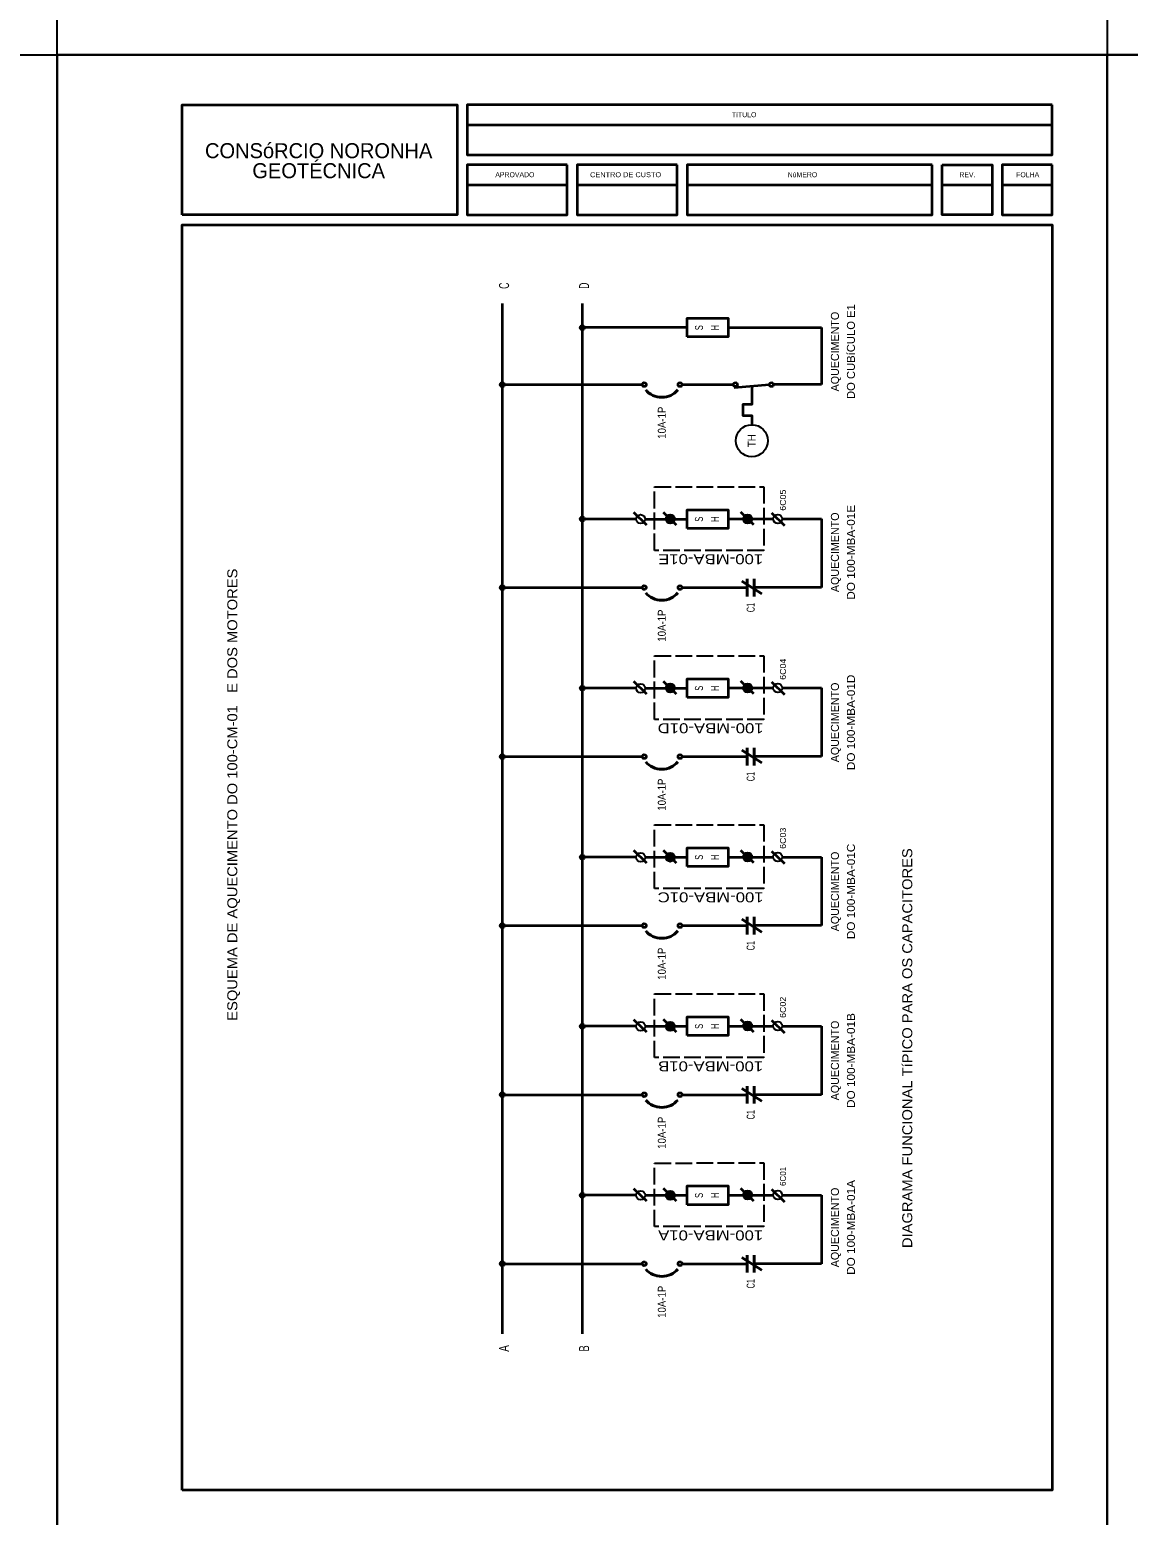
# Model space of a CAD drawing. Extents: x -4160 to -2690, y -474 to 714.
# Drawn here: x -3535.3 to -3315.6, y -171.5 to 125.5 of the extents above; entities that cross this region are included whole.
import ezdxf
from ezdxf.enums import TextEntityAlignment as Align

# ---------------------------------------------------------------- set-up
doc = ezdxf.new("R2010")
doc.units = 0
doc.header["$LTSCALE"] = 0.56
doc.linetypes.add('LONG_DASHED', pattern=[7.5, 6, -1.5])
doc.layers.add('2', color=7, linetype='Continuous', lineweight=25)
doc.layers.add('5', color=7, linetype='Continuous', lineweight=35)

msp = doc.modelspace()

# ---------------------------------------------------------------- hatches: boundary and pattern name
at = {"layer": '2'}
for points in [[(-3424.7533, 66.344, 1), (-3424.7533, 65.5189, 1)], [(-3440.7533, 54.931, 1), (-3440.7533, 54.1058, 1)], [(-3424.7533, 28.0555, 1), (-3424.7533, 27.2304, 1)], [(-3407.1695, 26.7464, 1), (-3407.1695, 28.5446, 1)], [(-3391.6888, 26.7816, 1), (-3391.6888, 28.5798, 1)], [(-3440.7533, 14.3678, 1), (-3440.7533, 13.5426, 1)], [(-3424.7533, -5.742, 1), (-3424.7533, -6.5671, 1)], [(-3407.1695, -7.0511, 1), (-3407.1695, -5.2529, 1)], [(-3391.6888, -7.0159, 1), (-3391.6888, -5.2177, 1)], [(-3440.7533, -19.4297, 1), (-3440.7533, -20.2549, 1)], [(-3424.7533, -39.5395, 1), (-3424.7533, -40.3647, 1)], [(-3407.1695, -40.8486, 1), (-3407.1695, -39.0504, 1)], [(-3391.6888, -40.8134, 1), (-3391.6888, -39.0152, 1)], [(-3440.7533, -53.2273, 1), (-3440.7533, -54.0524, 1)], [(-3424.7533, -73.337, 1), (-3424.7533, -74.1622, 1)], [(-3407.1695, -74.6461, 1), (-3407.1695, -72.848, 1)], [(-3391.6888, -74.6109, 1), (-3391.6888, -72.8128, 1)], [(-3440.7533, -87.0248, 1), (-3440.7533, -87.8499, 1)], [(-3407.1695, -108.4436, 1), (-3407.1695, -106.6455, 1)], [(-3391.6888, -108.4084, 1), (-3391.6888, -106.6103, 1)], [(-3424.7533, -107.1345, 1), (-3424.7533, -107.9597, 1)], [(-3440.7533, -120.8223, 1), (-3440.7533, -121.6475, 1)]]:
    msp.add_hatch(color=256, dxfattribs=at).paths.add_polyline_path(points)

# ---------------------------------------------------------------- linework, layer by layer
at = {"layer": '2', "lineweight": 35}
for p, q in [((-3440.7533, 70.7423), (-3440.7533, -135.2357)), ((-3424.7533, 70.7423), (-3424.7533, -135.2357)), ((-3403.7624, 65.9314), (-3424.7533, 65.9314)), ((-3395.5781, 65.9314), (-3376.9079, 65.9314)), ((-3376.9079, 65.9314), (-3376.9079, 54.5184)), ((-3440.7533, 54.5184), (-3412.7734, 54.5184)), ((-3404.8113, 54.5184), (-3394.5291, 54.5184)), ((-3387.3277, 54.4831), (-3394.3915, 53.8577)), ((-3376.9079, 54.5184), (-3386.5293, 54.5184)), ((-3413.981, 27.643), (-3424.7533, 27.643)), ((-3414.5149, 29.0213), (-3411.918, 26.5035)), ((-3412.183, 27.643), (-3403.7624, 27.643)), ((-3408.6024, 29.037), (-3406.0055, 26.5192)), ((-3395.5782, 27.6782), (-3386.5615, 27.6782)), ((-3393.1217, 29.0722), (-3390.5248, 26.5544)), ((-3384.2295, 26.2867), (-3386.8264, 28.8045)), ((-3384.7633, 27.6782), (-3376.9079, 27.6782)), ((-3376.9079, 27.6782), (-3376.9079, 13.9552)), ((-3392.8766, 15.2282), (-3388.8426, 12.6823)), ((-3440.7533, 13.9552), (-3412.7734, 13.9552)), ((-3404.8113, 13.9552), (-3391.8087, 13.9552)), ((-3376.9079, 13.9552), (-3390.3559, 13.9552)), ((-3414.5149, -4.7762), (-3411.918, -7.294)), ((-3408.6024, -4.7606), (-3406.0055, -7.2783)), ((-3393.1217, -4.7254), (-3390.5248, -7.2431)), ((-3384.2295, -7.5108), (-3386.8264, -4.993)), ((-3413.981, -6.1546), (-3424.7533, -6.1546)), ((-3412.183, -6.1546), (-3403.7624, -6.1546)), ((-3395.5782, -6.1194), (-3386.5615, -6.1194)), ((-3384.7633, -6.1194), (-3376.9079, -6.1194)), ((-3376.9079, -6.1194), (-3376.9079, -19.8423)), ((-3440.7533, -19.8423), (-3412.7734, -19.8423)), ((-3404.8113, -19.8423), (-3391.8087, -19.8423)), ((-3392.8766, -18.5694), (-3388.8426, -21.1152)), ((-3376.9079, -19.8423), (-3390.3559, -19.8423)), ((-3414.5149, -38.5738), (-3411.918, -41.0915)), ((-3408.6024, -38.5581), (-3406.0055, -41.0758)), ((-3393.1217, -38.5229), (-3390.5248, -41.0406)), ((-3413.981, -39.9521), (-3424.7533, -39.9521)), ((-3412.183, -39.9521), (-3403.7624, -39.9521)), ((-3395.5782, -39.9169), (-3386.5615, -39.9169)), ((-3384.2295, -41.3083), (-3386.8264, -38.7906)), ((-3384.7633, -39.9169), (-3376.9079, -39.9169)), ((-3376.9079, -39.9169), (-3376.9079, -53.6398)), ((-3392.8766, -52.3669), (-3388.8426, -54.9127)), ((-3440.7533, -53.6398), (-3412.7734, -53.6398)), ((-3404.8113, -53.6398), (-3391.8087, -53.6398)), ((-3376.9079, -53.6398), (-3390.3559, -53.6398)), ((-3413.981, -73.7496), (-3424.7533, -73.7496)), ((-3414.5149, -72.3713), (-3411.918, -74.889)), ((-3412.183, -73.7496), (-3403.7624, -73.7496)), ((-3408.6024, -72.3556), (-3406.0055, -74.8734)), ((-3395.5782, -73.7144), (-3386.5615, -73.7144)), ((-3393.1217, -72.3204), (-3390.5248, -74.8382)), ((-3384.2295, -75.1058), (-3386.8264, -72.5881)), ((-3384.7633, -73.7144), (-3376.9079, -73.7144)), ((-3376.9079, -73.7144), (-3376.9079, -87.4374)), ((-3440.7533, -87.4374), (-3412.7734, -87.4374)), ((-3404.8113, -87.4374), (-3391.8087, -87.4374)), ((-3392.8766, -86.1644), (-3388.8426, -88.7102)), ((-3376.9079, -87.4374), (-3390.3559, -87.4374)), ((-3414.5149, -106.1688), (-3411.918, -108.6866)), ((-3408.6024, -106.1531), (-3406.0055, -108.6709)), ((-3393.1217, -106.1179), (-3390.5248, -108.6357)), ((-3384.2295, -108.9034), (-3386.8264, -106.3856)), ((-3413.981, -107.5471), (-3424.7533, -107.5471)), ((-3412.183, -107.5471), (-3403.7624, -107.5471)), ((-3395.5782, -107.5119), (-3386.5615, -107.5119)), ((-3384.7633, -107.5119), (-3376.9079, -107.5119)), ((-3376.9079, -107.5119), (-3376.9079, -121.2349)), ((-3440.7533, -121.2349), (-3412.7734, -121.2349)), ((-3404.8113, -121.2349), (-3391.8087, -121.2349)), ((-3392.8766, -119.9619), (-3388.8426, -122.5078)), ((-3376.9079, -121.2349), (-3390.3559, -121.2349))]:
    msp.add_line(p, q, dxfattribs=at)
at = {"layer": '2', "lineweight": 40}
for p, q in [((-3391.8087, 12.1981), (-3391.8087, 15.6966)), ((-3390.3559, 12.1981), (-3390.3559, 15.6966)), ((-3391.8087, -21.5994), (-3391.8087, -18.1009)), ((-3390.3559, -21.5994), (-3390.3559, -18.1009)), ((-3391.8087, -55.397), (-3391.8087, -51.8984)), ((-3390.3559, -55.397), (-3390.3559, -51.8984)), ((-3391.8087, -89.1945), (-3391.8087, -85.6959)), ((-3390.3559, -89.1945), (-3390.3559, -85.6959)), ((-3391.8087, -122.992), (-3391.8087, -119.4934)), ((-3390.3559, -122.992), (-3390.3559, -119.4934))]:
    msp.add_line(p, q, dxfattribs=at)
at = {"layer": '2', "lineweight": 35}
for points in [[(-3403.7623, 64.0556), (-3403.7623, 67.8072), (-3395.5781, 67.8072), (-3395.5781, 64.0556)], [(-3403.7624, 25.7671), (-3403.7624, 29.5187), (-3395.5782, 29.5187), (-3395.5782, 25.7671)], [(-3403.7624, -8.0304), (-3403.7624, -4.2788), (-3395.5782, -4.2788), (-3395.5782, -8.0304)], [(-3403.7624, -41.8279), (-3403.7624, -38.0763), (-3395.5782, -38.0763), (-3395.5782, -41.8279)], [(-3403.7624, -75.6254), (-3403.7624, -71.8738), (-3395.5782, -71.8738), (-3395.5782, -75.6254)], [(-3403.7624, -109.423), (-3403.7624, -105.6714), (-3395.5782, -105.6714), (-3395.5782, -109.423)]]:
    msp.add_lwpolyline(points, close=True, dxfattribs=at)
msp.add_lwpolyline([(-3390.8596, 54.1704), (-3390.8596, 50.5766), (-3392.6703, 50.5766), (-3392.6703, 48.3522), (-3390.8596, 48.3636), (-3390.8596, 46.5087)], dxfattribs=at)
at = {"layer": '2', "linetype": 'LONG_DASHED'}
for points in [[(-3410.3205, 21.3845), (-3410.3205, 34.0927), (-3388.4367, 34.1148), (-3388.4239, 21.3845)], [(-3410.3205, -12.413), (-3410.3205, 0.2952), (-3388.4367, 0.3173), (-3388.4239, -12.413)], [(-3410.3205, -46.2106), (-3410.3205, -33.5023), (-3388.4367, -33.4802), (-3388.4239, -46.2106)], [(-3410.3205, -80.0081), (-3410.3205, -67.2998), (-3388.4367, -67.2778), (-3388.4239, -80.0081)], [(-3410.3205, -113.8056), (-3410.3205, -101.0974), (-3388.4367, -101.0753), (-3388.4239, -113.8056)]]:
    msp.add_lwpolyline(points, close=True, dxfattribs=at)
at = {"layer": '2', "lineweight": 35}
for centre, radius in [((-3424.7533, 65.9314), 0.4126), ((-3440.7533, 54.5184), 0.4126), ((-3412.3734, 54.5184), 0.4), ((-3405.2113, 54.5184), 0.4), ((-3394.1291, 54.5184), 0.4), ((-3386.9292, 54.5184), 0.4), ((-3424.7533, 27.643), 0.4126), ((-3440.7533, 13.9552), 0.4126), ((-3412.3734, 13.9552), 0.4), ((-3405.2113, 13.9552), 0.4), ((-3424.7533, -6.1546), 0.4126), ((-3440.7533, -19.8423), 0.4126), ((-3412.3734, -19.8423), 0.4), ((-3405.2113, -19.8424), 0.4), ((-3424.7533, -39.9521), 0.4126), ((-3440.7533, -53.6398), 0.4126), ((-3412.3734, -53.6398), 0.4), ((-3405.2113, -53.6399), 0.4), ((-3424.7533, -73.7496), 0.4126), ((-3440.7533, -87.4374), 0.4126), ((-3412.3734, -87.4373), 0.4), ((-3405.2113, -87.4374), 0.4), ((-3424.7533, -107.5471), 0.4126), ((-3440.7533, -121.2349), 0.4126), ((-3412.3734, -121.2348), 0.4), ((-3405.2113, -121.2349), 0.4)]:
    msp.add_circle(centre, radius, dxfattribs=at)
at = {"layer": '2'}
for centre, radius in [((-3390.8596, 43.3104), 3.1984), ((-3413.082, 27.6298), 0.8991), ((-3407.1695, 27.6455), 0.8991), ((-3391.6888, 27.6807), 0.8991), ((-3385.6624, 27.6782), 0.8991), ((-3413.082, -6.1677), 0.8991), ((-3407.1695, -6.152), 0.8991), ((-3391.6888, -6.1168), 0.8991), ((-3385.6624, -6.1194), 0.8991), ((-3413.082, -39.9652), 0.8991), ((-3407.1695, -39.9495), 0.8991), ((-3391.6888, -39.9143), 0.8991), ((-3385.6624, -39.9169), 0.8991), ((-3413.082, -73.7627), 0.8991), ((-3407.1695, -73.747), 0.8991), ((-3391.6888, -73.7118), 0.8991), ((-3385.6624, -73.7144), 0.8991), ((-3413.082, -107.5602), 0.8991), ((-3407.1695, -107.5446), 0.8991), ((-3391.6888, -107.5094), 0.8991), ((-3385.6624, -107.5119), 0.8991)]:
    msp.add_circle(centre, radius, dxfattribs=at)
at = {"layer": '2', "lineweight": 40}
for centre in [(-3408.8584, 55.2333), (-3408.8584, 14.6701), (-3408.8584, -19.1274), (-3408.8584, -52.9249), (-3408.8584, -86.7224), (-3408.8584, -120.5199)]:
    msp.add_ellipse(centre, major_axis=(-3.8115, 0), ratio=0.85, start_param=0.57974073, end_param=2.56185197, dxfattribs=at)
at = {"layer": '5', "lineweight": 25}
for p, q in [((-3529.7642, 120.48), (-3529.7642, 417.4797)), ((-3319.7642, 417.48), (-3319.7642, 120.48)), ((-3739.7642, 120.48), (-3529.7642, 120.48)), ((-3319.7642, 120.48), (-3529.7642, 120.48)), ((-3529.7642, -176.52), (-3529.7642, 120.48)), ((-3529.7642, 120.48), (-3529.7642, -176.52)), ((-3109.7642, 120.48), (-3319.7642, 120.48))]:
    msp.add_line(p, q, dxfattribs=at)
at = {"layer": '5'}
for p, q in [((-3447.7642, 106.48), (-3330.7642, 106.48)), ((-3447.7642, 94.48), (-3427.7642, 94.48)), ((-3425.7642, 94.48), (-3405.7642, 94.48)), ((-3403.7642, 94.48), (-3354.7642, 94.48)), ((-3352.7642, 94.48), (-3342.7642, 94.48)), ((-3340.7642, 94.48), (-3330.7642, 94.48))]:
    msp.add_line(p, q, dxfattribs=at)
at = {"layer": '5', "lineweight": 25}
msp.add_lwpolyline([(-3529.7642, 417.48), (-3319.7642, 417.48), (-3319.7642, 120.48)], dxfattribs=at)
for points in [[(-3319.7642, -176.52), (-3529.7642, -176.52), (-3529.7642, 120.48), (-3319.7642, 120.48)], [(-3109.7642, -176.52), (-3319.7642, -176.52), (-3319.7642, 120.48), (-3109.7642, 120.48)]]:
    msp.add_lwpolyline(points, close=True, dxfattribs=at)
at = {"layer": '5'}
for points in [[(-3504.7642, 88.48), (-3504.7642, 110.48), (-3449.7642, 110.48), (-3449.7642, 88.48)], [(-3330.7642, 110.48), (-3447.7642, 110.48), (-3447.7642, 100.48), (-3330.7642, 100.48)], [(-3427.7642, 98.48), (-3447.7642, 98.48), (-3447.7642, 88.48), (-3427.7642, 88.48)], [(-3405.7642, 98.48), (-3425.7642, 98.48), (-3425.7642, 88.48), (-3405.7642, 88.48)], [(-3354.7642, 98.48), (-3403.7642, 98.48), (-3403.7642, 88.48), (-3354.7642, 88.48)], [(-3352.7642, 98.48), (-3342.7642, 98.48), (-3342.7642, 88.48), (-3352.7642, 88.48)], [(-3330.7642, 98.48), (-3340.7642, 98.48), (-3340.7642, 88.48), (-3330.7642, 88.48)], [(-3504.7642, -166.52), (-3504.7642, 86.48), (-3330.7642, 86.48), (-3330.7642, -166.52)]]:
    msp.add_lwpolyline(points, close=True, dxfattribs=at)

# ---------------------------------------------------------------- texts
at = {"layer": '2'}
for s, height, rotation, width, p in [('C', 2, 90, 0.65, (-3439.4011, 74.2965)), ('D', 2, 90, 0.65, (-3423.4011, 74.2965)), ('DO CUBíCULO E1', 1.6, 90, 1.05, (-3370.2333, 61.1305)), ('S', 1.6, 90, 0.7, (-3400.6274, 65.9142)), ('H', 1.6, 90, 0.6, (-3397.4274, 65.9125)), ('10A-1P', 1.6, 90, 0.9, (-3408.0544, 46.9099)), ('TH', 1.6, 90, 0.9, (-3390.0597, 43.3103)), ('6C05', 1.2, 90, 1.1, (-3384.0321, 31.4268)), ('DO 100-MBA-01E', 1.6, 90, 1.1, (-3370.2333, 21.0051)), ('S', 1.6, 90, 0.7, (-3400.6275, 27.6257)), ('H', 1.6, 90, 0.6, (-3397.4275, 27.624)), ('100-MBA-01E', 2, 180, 1.25, (-3399.0881, 20.6254)), ('ESQUEMA DE AQUECIMENTO DO 100-CM-01   E DOS MOTORES', 2, 90, 1.1, (-3493.7471, -27.4534)), ('10A-1P', 1.6, 90, 0.9, (-3408.0544, 6.3467)), ('C1', 1.6, 90, 0.55, (-3390.2844, 9.9611)), ('6C04', 1.2, 90, 1.1, (-3384.0321, -2.3708)), ('S', 1.6, 90, 0.7, (-3400.6275, -6.1718)), ('H', 1.6, 90, 0.6, (-3397.4275, -6.1735)), ('DO 100-MBA-01D', 1.6, 90, 1.1, (-3370.2333, -13.0044)), ('100-MBA-01D', 2, 180, 1.25, (-3399.0882, -13.1722)), ('C1', 1.6, 90, 0.55, (-3390.2844, -23.8365)), ('10A-1P', 1.6, 90, 0.9, (-3408.0544, -27.4508)), ('6C03', 1.2, 90, 1.1, (-3384.0321, -36.1683)), ('DO 100-MBA-01C', 1.6, 90, 1.1, (-3370.2333, -46.802)), ('DIAGRAMA FUNCIONAL TíPICO PARA OS CAPACITORES', 2, 90, 1.1, (-3358.7702, -78.1262)), ('S', 1.6, 90, 0.7, (-3400.6275, -39.9693)), ('H', 1.6, 90, 0.6, (-3397.4275, -39.971)), ('100-MBA-01C', 2, 180, 1.25, (-3399.0882, -46.9697)), ('10A-1P', 1.6, 90, 0.9, (-3408.0544, -61.2483)), ('C1', 1.6, 90, 0.55, (-3390.2844, -57.634)), ('6C02', 1.2, 90, 1.1, (-3384.0321, -69.9658)), ('DO 100-MBA-01B', 1.6, 90, 1.1, (-3370.2333, -80.5994)), ('S', 1.6, 90, 0.7, (-3400.6275, -73.7668)), ('H', 1.6, 90, 0.6, (-3397.4275, -73.7685)), ('100-MBA-01B', 2, 180, 1.25, (-3399.0882, -80.7672)), ('10A-1P', 1.6, 90, 0.9, (-3408.0544, -95.0458)), ('C1', 1.6, 90, 0.55, (-3390.2844, -91.4315)), ('DO 100-MBA-01A', 1.6, 90, 1.1, (-3370.2333, -113.9731)), ('S', 1.6, 90, 0.7, (-3400.6275, -107.5643)), ('H', 1.6, 90, 0.6, (-3397.4275, -107.5661)), ('100-MBA-01A', 2, 180, 1.25, (-3399.0882, -114.5647)), ('C1', 1.6, 90, 0.55, (-3390.2844, -125.229)), ('10A-1P', 1.6, 90, 0.9, (-3408.0544, -128.8433)), ('A', 2, 90, 0.75, (-3439.4011, -138.1615)), ('B', 2, 90, 0.7, (-3423.4011, -138.1615))]:
    msp.add_text(s, height=height, rotation=rotation, dxfattribs=dict(at, width=width)).set_placement(p, align=Align.CENTER)
for s, height, p in [('AQUECIMENTO', 1.6, (-3373.4333, 61.1306)), ('AQUECIMENTO', 1.6, (-3373.4333, 21.0051)), ('AQUECIMENTO', 1.6, (-3373.4333, -13.0043)), ('AQUECIMENTO', 1.6, (-3373.4333, -46.8019)), ('AQUECIMENTO', 1.6, (-3373.4333, -80.5994)), ('6C01', 1.2, (-3384.0321, -103.7633)), ('AQUECIMENTO', 1.6, (-3373.4333, -113.9731))]:
    msp.add_text(s, height=height, rotation=90, dxfattribs=at).set_placement(p, align=Align.CENTER)
at = {"layer": '5'}
for s, height, p in [('TíTULO', 1, (-3392.3847, 107.991)), ('CONSóRCIO NORONHA', 3, (-3477.4749, 99.7961)), ('GEOTÉCNICA', 3, (-3477.475, 95.7961)), ('APROVADO', 1, (-3438.2387, 95.9973)), ('REV.', 1, (-3347.7443, 95.9923)), ('FOLHA', 1, (-3335.6809, 95.9923))]:
    msp.add_text(s, height=height, dxfattribs=at).set_placement(p, align=Align.CENTER)
for s, width, p in [('CENTRO DE CUSTO', 1.1, (-3416.0934, 95.9973)), ('NúMERO', 0.95, (-3380.7228, 95.9923))]:
    msp.add_text(s, height=1, dxfattribs=dict(at, width=width)).set_placement(p, align=Align.CENTER)

doc.saveas('drawing.dxf')
